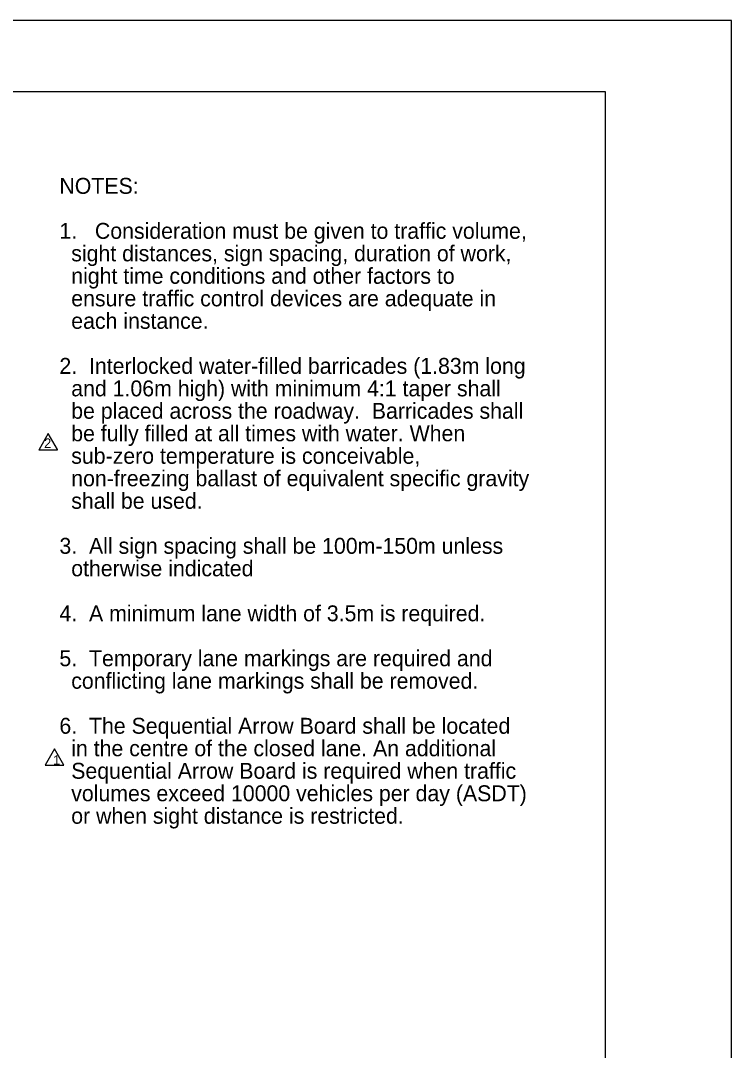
# Model space of a CAD drawing. Extents: x 2157 to 2399, y 147 to 426.
# Drawn here: x 2290.7 to 2398.7, y 269.5 to 426 of the extents above; entities that cross this region are included whole.
import ezdxf

# ---------------------------------------------------------------- set-up
doc = ezdxf.new("R2010")
doc.units = 0
for name, color, linetype in [('Level 1', 7, 'Continuous'), ('Level 10', 7, 'Continuous'), ('Level 29', 7, 'Continuous'), ('Level 60', 7, 'Continuous')]:
    doc.layers.add(name, color=color, linetype=linetype)

# ---------------------------------------------------------------- blocks, each defined once
blk = doc.blocks.new('REV1')
at = {"layer": 'Level 1'}
blk.add_lwpolyline([(0.114, 1.689), (-1.305, -0.781), (1.533, -0.781)], close=True, dxfattribs=at)
blk.add_text('1', height=1.448, rotation=360, dxfattribs=at).set_placement((-0.113, -0.724))
blk = doc.blocks.new('APRNTR')
at = {"layer": 'Level 60'}
blk.add_line((19.126, 268.191), (19.126, 268.191), dxfattribs=at)
for points in [[(19.126, 268.191), (-196.874, 268.191), (-196.874, -10.809), (19.126, -10.809)], [(0, 257.382), (-186.874, 257.382), (-186.874, 0), (0, 0)]]:
    blk.add_lwpolyline(points, close=True, dxfattribs=at)

msp = doc.modelspace()

# ---------------------------------------------------------------- linework, layer by layer
at = {"layer": 'Level 29'}
for points in [[(2294.92, 363.23), (2293.52, 360.8)], [(2296.31, 360.8), (2294.92, 363.23)], [(2293.52, 360.8), (2293.5, 360.76), (2296.34, 360.76), (2296.31, 360.8)]]:
    msp.add_lwpolyline(points, dxfattribs=at)

# ---------------------------------------------------------------- block references
at = {"layer": 'Level 10'}
for name, p in [('APRNTR', (2379.59, 157.8)), ('REV1', (2295.76, 313.6))]:
    msp.add_blockref(name, p, dxfattribs=at)

# ---------------------------------------------------------------- texts
for s, p in [('NOTES:', (2296.61, 399.66)), ('1.   Consideration must be given to traffic volume, ', (2296.61, 392.82)), ('  sight distances, sign spacing, duration of work, ', (2296.61, 389.4)), ('  night time conditions and other factors to ', (2296.61, 385.98)), ('  ensure traffic control devices are adequate in ', (2296.61, 382.56)), ('  each instance.', (2296.61, 379.14)), ('2.  Interlocked water-filled barricades (1.83m long', (2296.61, 372.3)), ('  and 1.06m high) with minimum 4:1 taper shall ', (2296.61, 368.88)), ('  be placed across the roadway.  Barricades shall', (2296.61, 365.47)), ('  be fully filled at all times with water. When ', (2296.61, 362.05)), ('  sub-zero temperature is conceivable, ', (2296.61, 358.63)), ('  non-freezing ballast of equivalent specific gravity', (2296.61, 355.21)), ('  shall be used.    ', (2296.61, 351.79)), ('3.  All sign spacing shall be 100m-150m unless ', (2296.61, 344.95)), ('  otherwise indicated', (2296.61, 341.53)), ('4.  A minimum lane width of 3.5m is required.', (2296.61, 334.69)), ('5.  Temporary lane markings are required and ', (2296.61, 327.86)), ('  conflicting lane markings shall be removed.', (2296.61, 324.44)), ('6.  The Sequential Arrow Board shall be located ', (2296.61, 317.6)), ('  in the centre of the closed lane. An additional ', (2296.61, 314.18)), ('  Sequential Arrow Board is required when traffic ', (2296.61, 310.76)), ('  volumes exceed 10000 vehicles per day (ASDT) ', (2296.61, 307.34)), ('  or when sight distance is restricted. ', (2296.61, 303.92))]:
    msp.add_text(s, height=2.419, dxfattribs=at).set_placement(p)
msp.add_text('2', height=1.45, rotation=360, dxfattribs=at).set_placement((2294.29, 361.03))

doc.saveas('drawing.dxf')
